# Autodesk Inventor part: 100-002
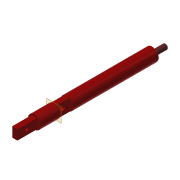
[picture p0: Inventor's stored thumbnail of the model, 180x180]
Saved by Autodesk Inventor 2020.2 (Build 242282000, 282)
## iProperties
Created: 2014-01
Part Number: 100-002
Material: Ogólny
Document SubType Name: Modeling
Designer: F.Stasiak
Density: 1 g/cm^3
Appearance: Czerwona
Manager: www.cadconsulting.pl
Company: Fabian Stasiak CAD Consulting
Author: F.Stasiak
Subject: Zbiór ćwiczeń. Autodesk Inventor 2020. Kurs podstawowy
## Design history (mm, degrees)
sketch "Szkic1"
  geometry: C1 r 10 at (0, 0); 1 further point
  constraints: 1 centre point, 1 coincident
  dimensions: "d0" = 20 diameter of C1
extrude "Wyciągnięcie proste1" new body sketch "Szkic1" distance "d1" = 200; taper "d2" = 0 deg
sketch "Szkic2"
  geometry: L1 (-4, 7.5)-(4, 7.5); L2 (4, 7.5)-(4, -7.5); L3 (4, -7.5)-(-4, -7.5); L4 (-4, -7.5)-(-4, 7.5); L5 (-4, 7.5)-(4, -7.5); L6 (4, 7.5)-(-4, -7.5); C1 r 10 at (0, 0) reference
  constraints: 12 end point, 2 midpoint, 2 parallel, 1 horizontal, 1 perpendicular
  dimensions: "d3" = 8 distance of L2.end L3.end; "d4" = 15 distance of L1.end L2.end
extrude "Wyciągnięcie proste2" join sketch "Szkic2" distance "d5" = 30; taper "d6" = 0 deg
sketch "Szkic3"
  geometry: L1 (0, 15)-(-30, 15) reference; L2 (-30, 0)-(-30, 15) reference; 4 further points
  constraints: 2 midpoint, 1 horizontal alignment, 1 vertical alignment
hole "Otwór1" sketch "Szkic3" at (-15, 7.5) diameter "d7" = 5.5; stored, may be unused: countersink angle "d11" = 90 deg, drill point angle "d13" = 118 deg; dims "d8" = 6, "d9" = 4, "d10" = 2, "d12" = 8
node "Płaszczyzna konstrukcyjna1"
sketch "Szkic4"
  geometry: L1 (4, -7.5)-(4, 7.5) reference; L2 (-4, 7.5)-(-4, -7.5) reference; L3 (-4, 7.5)-(-4, 9.165); L4 (4, 7.5)-(4, 9.165); L5 (4, -7.5)-(4, -9.165); L6 (-4, -7.5)-(-4, -9.165); A1 r 10 centre (0, 0) between (-4, 9.165) and (4, 9.165) reference; A2 r 10 centre (0, 0) between (-4, 9.165) and (4, 9.165) reference; 1 further point
  constraints: 8 end point, 8 point on circle, 4 collinear
extrude "Wyciągnięcie proste3" cut sketch "Szkic4" distance "d15" = 20; taper "d16" = 0 deg
sketch "Szkic5"
  geometry: L1 (0, 18.33)-(20, 18.33) reference; L2 (0, 18.33)-(0, 0) reference; 4 further points
  constraints: 2 midpoint, 1 horizontal alignment, 1 vertical alignment
hole "Otwór2" sketch "Szkic5" at (10, 9.165) diameter "d17" = 6.5; stored, may be unused: countersink angle "d21" = 90 deg, drill point angle "d23" = 118 deg; dims "d18" = 6, "d19" = 4, "d20" = 2, "d22" = 8
sketch "Szkic6"
  geometry: C1 r 10 at (0, 0) reference; C2 r 4 at (0, 0)
  constraints: 1 centre point
  dimensions: "d24" = 8 diameter of C2
extrude "Wyciągnięcie proste4" cut sketch "Szkic6" distance "d25" = 20; taper "d26" = 0 deg
feature "Gwint1" dims "d27" = 10, "d28" = 0
node "Bryła1"
node "Pętla rzutowana1"
